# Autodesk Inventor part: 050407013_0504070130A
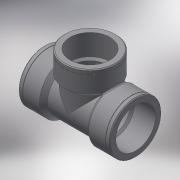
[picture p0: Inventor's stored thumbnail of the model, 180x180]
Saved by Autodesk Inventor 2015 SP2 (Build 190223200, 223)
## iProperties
Created: 2017-05
Part Number: 050407013_0504070130A
Material: Generic
Description: PLASSON THREADED TEE 1.1/4"
Document SubType Name: Modeling
Designer: KIM
Density: 1 g/cm^3
Appearance: Default
Author: KIM
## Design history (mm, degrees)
derived "050407.ipt"
feature "Solid1::050407.ipt"
tag "TaggingFeature1"
body "Solid1"
other parameters: "d0" = 48, "d2" = 0.5, "d3" = 0.5, "d4" = 50.6376, "d5" = 38.952, "d6" = 25, "d7" = 135 deg, "d8" = 28.75, "d9" = 4.79167, "d19" = 0.77904, "d27" = 25, "d30" = 35.0568, "d31" = 42.8472, "d33" = 180 deg, "d39" = 0, "d45" = 0, "d46" = 42.8472, "d48" = 0, "d50" = 0, "d51" = 1.16856, "Rp_" = 38.952, "H_" = 96, "l_2" = 25
